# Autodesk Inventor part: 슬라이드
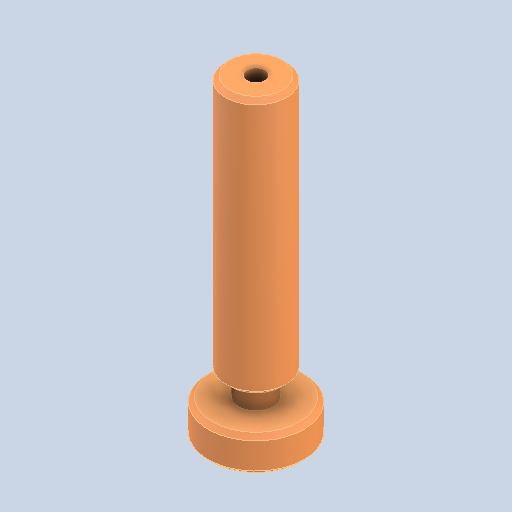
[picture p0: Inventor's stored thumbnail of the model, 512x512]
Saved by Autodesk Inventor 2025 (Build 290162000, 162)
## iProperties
Created: 2024-07
Part Number: 슬라이드
Material: 강철, 연강
Document SubType Name: Modeling
Designer: onair
Density: 7.86 g/cm^3
Appearance: 기본값
Author: jhkim
Sending System: Autodesk Inventor 2025
Preprocessor: ST-DEVELOPER v20
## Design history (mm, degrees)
feature "솔리드1"
node "솔리드2"
